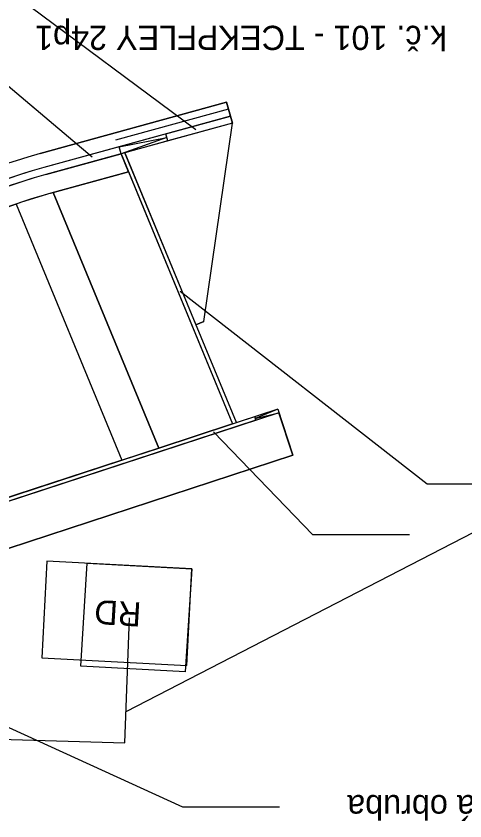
# Model space of a CAD drawing. Extents: x -728547 to -728179, y -1073068 to -1072839.
# Drawn here: x -728493.54 to -728484.26, y -1073041.14 to -1073024.51 of the extents above; entities that cross this region are included whole.
import ezdxf

# ---------------------------------------------------------------- set-up
doc = ezdxf.new("R2010")
doc.units = 0
for name, color, linetype in [('_NOR-návrh tenká', 7, 'Continuous'), ('_NOR-popis', 7, 'Continuous'), ('_NOR-VDZ', 7, 'Continuous'), ('_NOR-šraf_+-0', 7, 'Continuous'), ('_NOR-šraf_+12', 7, 'Continuous'), ('_NOR-šraf_+6', 7, 'Continuous'), ('_NOR-šraf_bezbariéra', 7, 'Continuous'), ('_NOR-šraf_chodník', 7, 'Continuous'), ('_NOR-šraf_signální pás', 7, 'Continuous'), ('_NOR-šraf_varovný pás', 7, 'Continuous'), ('_NOR-šraf_vozovka', 7, 'Continuous'), ('_NOR-šraf_zeleň', 7, 'Continuous'), ('KOS_kabelová trasa', 7, 'Continuous'), ('KOS_kabelová trasa popis', 7, 'Continuous'), ('KOS_nové prvky PZZ', 7, 'Continuous'), ('KTA_PZZ rušené', 7, 'Continuous')]:
    doc.layers.add(name, color=color, linetype=linetype)

msp = doc.modelspace()

# ---------------------------------------------------------------- linework, layer by layer
at = {"layer": '_NOR-návrh tenká'}
for p, q in [((-728489.66, -1073030.819), (-728489.068, -1073026.719)), ((-728489.068, -1073026.719), (-728489.108, -1073026.574)), ((-728491.408, -1073027.208), (-728490.424, -1073027.015)), ((-728490.424, -1073027.015), (-728491.368, -1073027.353)), ((-728490.404, -1073027.087), (-728490.444, -1073026.942)), ((-728491.368, -1073027.353), (-728491.408, -1073027.208)), ((-728491.368, -1073027.353), (-728489.062, -1073032.933)), ((-728492.771, -1073028.155), (-728490.59, -1073033.433)), ((-728493.539, -1073028.392), (-728491.352, -1073033.682)), ((-728489.66, -1073030.819), (-728489.821, -1073030.886)), ((-728488.131, -1073032.628), (-728488.594, -1073032.822)), ((-728488.594, -1073032.822), (-728488.106, -1073032.704)), ((-728488.131, -1073032.628), (-728487.82, -1073033.579))]:
    msp.add_line(p, q, dxfattribs=at)
for points in [[(-728489.108, -1073026.574), (-728489.188, -1073026.285), (-728493.044, -1073027.348)], [(-728489.108, -1073026.574), (-728492.964, -1073027.637)], [(-728489.068, -1073026.719), (-728492.924, -1073027.782)], [(-728488.985, -1073032.908), (-728491.29, -1073027.331)], [(-728491.214, -1073027.725), (-728492.818, -1073028.168)], [(-728488.131, -1073032.628), (-728496.655, -1073035.417)], [(-728488.106, -1073032.704), (-728496.63, -1073035.493)], [(-728488.581, -1073032.86), (-728488.606, -1073032.784)], [(-728487.82, -1073033.579), (-728495.393, -1073036.056)]]:
    msp.add_lwpolyline(points, dxfattribs=at)
for radius, end in [(12.3, 180.2086), (12, 180.2086), (11.85, 180.2086), (11.45, 117.2893)]:
    msp.add_arc((-728489.773, -1073039.206), radius, 105.42, end, dxfattribs=at)
at = {"layer": '_NOR-popis'}
for p, q in [((-728494.648, -1073023.263), (-728489.823, -1073026.852)), ((-728491.969, -1073027.422), (-728495.822, -1073024.175)), ((-728485.044, -1073034.178), (-728490.147, -1073030.2)), ((-728487.405, -1073035.225), (-728489.456, -1073033.101)), ((-728483.044, -1073034.178), (-728485.044, -1073034.178)), ((-728485.405, -1073035.225), (-728487.405, -1073035.225)), ((-728490.094, -1073040.851), (-728495.673, -1073038.306)), ((-728488.094, -1073040.851), (-728490.094, -1073040.851))]:
    msp.add_line(p, q, dxfattribs=at)
at = {"layer": '_NOR-VDZ'}
msp.add_lwpolyline([(-728489.148, -1073026.429), (-728491.483, -1073027.074)], dxfattribs=at)
at = {"layer": '_NOR-šraf_+-0'}
msp.add_lwpolyline([(-728488.985, -1073032.908), (-728491.29, -1073027.331), (-728491.368, -1073027.353), (-728491.214, -1073027.725), (-728489.062, -1073032.933), (-728488.985, -1073032.908)], dxfattribs=at)
at = {"layer": '_NOR-šraf_+12'}
msp.add_lwpolyline([(-728490.444, -1073026.942), (-728489.108, -1073026.574), (-728489.068, -1073026.719), (-728490.404, -1073027.087), (-728490.424, -1073027.015), (-728490.444, -1073026.942)], dxfattribs=at)
at = {"layer": '_NOR-šraf_+6'}
msp.add_lwpolyline([(-728496.655, -1073035.417), (-728491.352, -1073033.682), (-728490.59, -1073033.433), (-728489.062, -1073032.933), (-728488.985, -1073032.908), (-728488.606, -1073032.784), (-728488.594, -1073032.822), (-728488.581, -1073032.86), (-728496.554, -1073035.468), (-728496.63, -1073035.493), (-728496.655, -1073035.417), (-728496.655, -1073035.417)], dxfattribs=at)
at = {"layer": '_NOR-šraf_bezbariéra'}
msp.add_lwpolyline([(-728492.924, -1073027.782), (-728491.368, -1073027.353), (-728491.408, -1073027.208), (-728492.964, -1073027.637)], dxfattribs=at)
for radius in [12, 11.85]:
    msp.add_arc((-728489.773, -1073039.206), radius, 105.42, 117.0974, dxfattribs=at)
at = {"layer": '_NOR-šraf_chodník'}
for p, q in [((-728493.539, -1073028.392), (-728491.352, -1073033.682)), ((-728491.352, -1073033.682), (-728496.655, -1073035.417))]:
    msp.add_line(p, q, dxfattribs=at)
msp.add_lwpolyline([(-728490.59, -1073033.433), (-728492.771, -1073028.155), (-728491.214, -1073027.725), (-728489.062, -1073032.933), (-728490.59, -1073033.433)], dxfattribs=at)
at = {"layer": '_NOR-šraf_signální pás'}
for points in [[(-728490.59, -1073033.433), (-728492.771, -1073028.155), (-728492.818, -1073028.168)], [(-728493.539, -1073028.392), (-728491.352, -1073033.682), (-728490.59, -1073033.433), (-728490.59, -1073033.433)]]:
    msp.add_lwpolyline(points, dxfattribs=at)
msp.add_arc((-728489.773, -1073039.206), 11.45, 105.42, 109.1994, dxfattribs=at)
at = {"layer": '_NOR-šraf_varovný pás'}
msp.add_lwpolyline([(-728492.818, -1073028.168), (-728492.771, -1073028.155), (-728491.214, -1073027.725), (-728491.368, -1073027.353), (-728492.924, -1073027.782)], dxfattribs=at)
for radius, start, end in [(11.85, 105.42, 117.0974), (11.45, 105.42, 109.1994), (11.45, 109.1994, 117.2893)]:
    msp.add_arc((-728489.773, -1073039.206), radius, start, end, dxfattribs=at)
at = {"layer": '_NOR-šraf_vozovka'}
msp.add_lwpolyline([(-728493.044, -1073027.348), (-728489.188, -1073026.285), (-728489.108, -1073026.574), (-728491.408, -1073027.208), (-728492.964, -1073027.637)], dxfattribs=at)
for radius, end in [(12.3, 180.2086), (12, 117.0974)]:
    msp.add_arc((-728489.773, -1073039.206), radius, 105.42, end, dxfattribs=at)
at = {"layer": '_NOR-šraf_zeleň'}
for points in [[(-728489.821, -1073030.886), (-728489.66, -1073030.819), (-728489.068, -1073026.719), (-728490.404, -1073027.087), (-728491.29, -1073027.331), (-728489.821, -1073030.886), (-728489.821, -1073030.886)], [(-728496.554, -1073035.468), (-728494.744, -1073041), (-728493.757, -1073041.058), (-728495.393, -1073036.056), (-728487.82, -1073033.579), (-728488.106, -1073032.704), (-728496.554, -1073035.468)]]:
    msp.add_lwpolyline(points, dxfattribs=at)
at = {"layer": 'KOS_kabelová trasa'}
msp.add_lwpolyline([(-728494.829, -1073039.422), (-728493.88, -1073039.45), (-728491.292, -1073039.525), (-728491.192, -1073036.939)], dxfattribs=at)
at = {"layer": 'KOS_kabelová trasa popis'}
msp.add_line((-728479.858, -1073032.993), (-728491.268, -1073038.884), dxfattribs=at)
at = {"layer": 'KOS_nové prvky PZZ'}
msp.add_lwpolyline([(-728489.907, -1073035.925), (-728492.903, -1073035.767), (-728493.008, -1073037.764), (-728490.012, -1073037.922)], close=True, dxfattribs=at)
at = {"layer": 'KTA_PZZ rušené'}
msp.add_lwpolyline([(-728490.044, -1073038.056), (-728492.203, -1073037.942), (-728492.066, -1073035.811), (-728489.907, -1073035.925), (-728490.044, -1073038.056)], dxfattribs=at)

# ---------------------------------------------------------------- texts
at = {"layer": '_NOR-popis'}
msp.add_text('zapuštěná chodníková obruba', height=0.5, rotation=180, dxfattribs=at).set_placement((-728477.736, -1073040.601))
at = {"layer": 'KOS_kabelová trasa popis'}
msp.add_text('k.č. 101 - TCEKPFLEY 24p1', height=0.5, rotation=180, dxfattribs=at).set_placement((-728484.636, -1073024.709))
at = {"layer": 'KOS_nové prvky PZZ'}
msp.add_text('RD', height=0.5, rotation=176.5903, dxfattribs=at).set_placement((-728490.939, -1073036.625))

doc.saveas('drawing.dxf')
